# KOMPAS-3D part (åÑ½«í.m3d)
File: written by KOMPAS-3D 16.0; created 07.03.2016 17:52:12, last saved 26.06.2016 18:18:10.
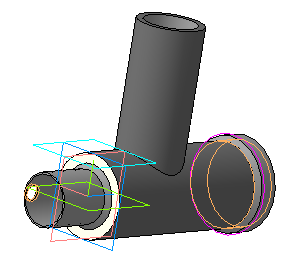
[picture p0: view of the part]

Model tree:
1. Эскиз:1
2. Операция выдавливания:1
     Расстояние 1 = 115
3. Эскиз:2
4. Операция выдавливания:2
     Расстояние 1 = 20
5. Смещенная плоскость:1
     Расстояние = 25
6. Эскиз:3
7. Операция выдавливания:3
     Расстояние 1 = 75
8. Операция выдавливания:4
     Расстояние 1 = 10.0003
9. Фаска:1
     Угол = 45; Длина 1 = 4; Длина 2 = 4
10. Эскиз:4
11. Вырезать элемент выдавливания:1
     Расстояние 1 = 106
12. Эскиз:5
13. Вырезать элемент выдавливания:2
     Расстояние 1 = 20
14. Эскиз:7
15. Операция выдавливания:5
     Расстояние 1 = 36; На расстояние 1 = 20
16. Эскиз:6
17. Вырезать элемент выдавливания:3
     Расстояние 1 = 110
18. Эскиз:8
19. Вырезать элемент выдавливания:4
     Расстояние 1 = 110
20. Фаска:3
     Угол = 45; Длина 1 = 3; Длина 2 = 3
21. Эскиз:9
22. Операция выдавливания:6
     Расстояние 1 = 8; Расстояние 2 = 52
23. Массив по концентрической сетке:1  (with: Операция выдавливания:6, Эскиз:9)  (12 pattern instances)
     Геометрический массив = 11; Шаг 2 = 360
24. Вырезать элемент выдавливания:5
     Расстояние 1 = 10
25. Условное изображение резьбы:11  (labels: E:\Sys\Thread\cil0_8724-2002 coarse.xml; M56)
     Шаг резьбы = 5.5; Номинальный диаметр резьбы = 56
26. Подгонка:3
27. Эскиз:10
28. Эскиз:11
29. Вырезать элемент выдавливания:6
     Расстояние 1 = 32
30. Условное изображение резьбы:12  (labels: E:\Sys\Thread\cil0_8724-2002 fine.xml; M10x1)
     Длина резьбы = 1; Шаг резьбы = 1; Номинальный диаметр резьбы = 10
31. Подгонка:1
